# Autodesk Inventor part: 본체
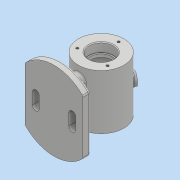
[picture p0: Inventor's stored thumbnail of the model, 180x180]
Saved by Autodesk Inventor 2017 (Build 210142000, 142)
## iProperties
Part Number: 본체
Material: 일반
Document SubType Name: Modeling
Designer: 601-07
Density: 1 g/cm^3
Appearance: 기본값
Mass: 183.432 g
Surface Area: 489.781 cm^2
Volume: 183.432 cm^3
Author: 601-07
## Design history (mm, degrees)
sketch "스케치1"
  geometry: C1 r 30 at (0, 0); 1 further point
  constraints: 1 centre point, 1 coincident
  dimensions: "d0" = 60 diameter of C1
extrude "돌출1" new body sketch "스케치1" stored distance "d1" = 72; taper "d2" = 0 deg
node "작업 평면1"
sketch "스케치2"
  geometry: L1 (38, 35.496)-(-38, 35.496); L2 (-38, 35.496)-(-38, -35.496); L3 (-38, -35.496)-(38, -35.496); L4 (38, -35.496)-(38, 35.496); A1 r 52 centre (0, 0) between (38, 35.496) and (-38, 35.496); A2 r 52 centre (0, 0) between (-38, -35.496) and (38, -35.496); 1 further point
  constraints: 8 end point, 4 point on circle, 2 centre point, 2 parallel, 1 coincident, 1 horizontal, 1 perpendicular
  dimensions: "d5" = 76 distance of L1.start L1.end; "d6" = 52 radius of A2; "d7" = 52 radius of A1
extrude "돌출2" join sketch "스케치2" distance "d8" = 10; taper "d9" = 0 deg
sketch "스케치3"
  geometry: L1 (0, -19)-(0, 19); L2 (7, -19)-(7, 19); L3 (-7, 19)-(-7, -19); A1 r 7 centre (0, -19) between (-7, -19) and (7, -19); A2 r 7 centre (0, 19) between (7, 19) and (-7, 19); 2 further points
  constraints: 8 end point, 4 point on circle, 4 tangent, 2 centre point, 1 coincident, 1 midpoint, 1 parallel, 1 vertical
  dimensions: "d10" = 38 distance of L1.start L1.end; "d11" = 14 distance between parallel lines of L2 L3
extrude "돌출3" join sketch "스케치3" stored distance "d12" = 10; taper "d13" = 0 deg
sketch "스케치4"
  geometry: C1 r 16 at (0, 0); 1 further point
  constraints: 1 centre point, 1 coincident
  dimensions: "d14" = 32 diameter of C1
extrude "돌출4" cut sketch "스케치4" distance "d15" = 12; taper "d16" = 0 deg
sketch "스케치5"
  geometry: C1 r 14 at (0, 0); 1 further point
  constraints: 1 centre point, 1 coincident
  dimensions: "d17" = 28 diameter of C1
extrude "돌출5" cut sketch "스케치5" distance "d18" = 4; taper "d19" = 0 deg
sketch "스케치6"
  geometry: C1 r 25 at (0, 0); 1 further point
  constraints: 1 centre point, 1 coincident
  dimensions: "d20" = 50 diameter of C1
extrude "돌출6" cut sketch "스케치6" distance "d21" = 40; taper "d22" = 0 deg
sketch "스케치7"
  geometry: C1 r 14 at (0, 0); 1 further point
  constraints: 1 centre point, 1 coincident
  dimensions: "d23" = 28 diameter of C1
extrude "돌출7" cut sketch "스케치7" distance "d24" = 4; taper "d25" = 0 deg
sketch "스케치8"
  geometry: C1 r 16 at (0, 0); 1 further point
  constraints: 1 centre point, 1 coincident
  dimensions: "d26" = 32 diameter of C1
extrude "돌출8" cut sketch "스케치8" distance "d27" = 12; taper "d28" = 0 deg
sketch "스케치9"
  geometry: 2 further points
  constraints: 1 vertical alignment
  dimensions: "d29" = 23 distance of point (0, 0) point (0, 23)
hole "구멍1" sketch "스케치9" at (0, 23) diameter "d30" = 3.242; stored, may be unused: countersink angle "d34" = 90 deg, drill point angle "d36" = 118 deg; dims "d31" = 8, "d32" = 4, "d33" = 2, "d35" = 10
chamfer "모따기1" distance "d40" = 1; stored, may be unused: second distance "d41" = 2, angle "d42" = 45 deg
fillet "모깎기1" dims "d43" = 0.3
fillet "모깎기2" dims "d44" = 3
sketch "스케치11"
  geometry: L1 (0, 0)-(0, 37.076); L2 (0, 0)-(16.5, 28.579)
  constraints: 4 end point, 1 vertical
  dimensions: "d45" = 33 distance of L1.start L2.end; "d46" = 30 deg angle of L1 L2
node "작업 평면2"
sketch "스케치12"
  geometry: C1 r 8 at (0, 0); 1 further point
  constraints: 1 centre point, 1 coincident
  dimensions: "d47" = 16 diameter of C1
extrude "돌출9" join sketch "스케치12" stored distance "d48" = 6.25; taper "d49" = 0 deg
sketch "스케치13"
  geometry: C1 r 4 at (0, 0); 1 further point
  constraints: 1 centre point, 1 coincident
  dimensions: "d50" = 8 diameter of C1
extrude "돌출10" cut sketch "스케치13" distance "d51" = 16.5; taper "d52" = 0 deg
fillet "모깎기3" dims "d53" = 1
sketch "스케치14"
  geometry: L1 (-24, -7.5)-(-24, 7.5); L2 (-19.5, -7.5)-(-19.5, 7.5); L3 (-28.5, 7.5)-(-28.5, -7.5); A1 r 4.5 centre (-24, -7.5) between (-28.5, -7.5) and (-19.5, -7.5); A2 r 4.5 centre (-24, 7.5) between (-19.5, 7.5) and (-28.5, 7.5); 2 further points
  constraints: 8 end point, 4 point on circle, 4 tangent, 2 centre point, 1 horizontal alignment, 1 midpoint, 1 parallel, 1 vertical
  dimensions: "d57" = 9 distance between parallel lines of L2 L3; "d58" = 15 distance of L1.start L1.end; "d59" = 24 distance from line of point (0, 0) L1
extrude "돌출11" cut sketch "스케치14" distance "d60" = 16.5; taper "d61" = 0 deg
fillet "모깎기4" dims "d62" = 3
fillet "모깎기5" dims "d63" = 3
sketch "스케치15"
  geometry: C1 r 42.5 at (0, 0); 1 further point
  constraints: 1 centre point, 1 coincident, 1 other
  dimensions: "d64" = 85 diameter of C1
feature "엠보싱1" sketch "스케치15" dims "d65" = 0.5, "d66" = 0
fillet "모깎기6" dims "d67" = 3
fillet "모깎기7" dims "d68" = 1
node "솔리드1"
pattern_circular "원형 패턴1" dims angle "d38" = 360 deg
mirror "미러1"
mirror "미러2"
other parameters: "d3" = -62, "d4" = 104
